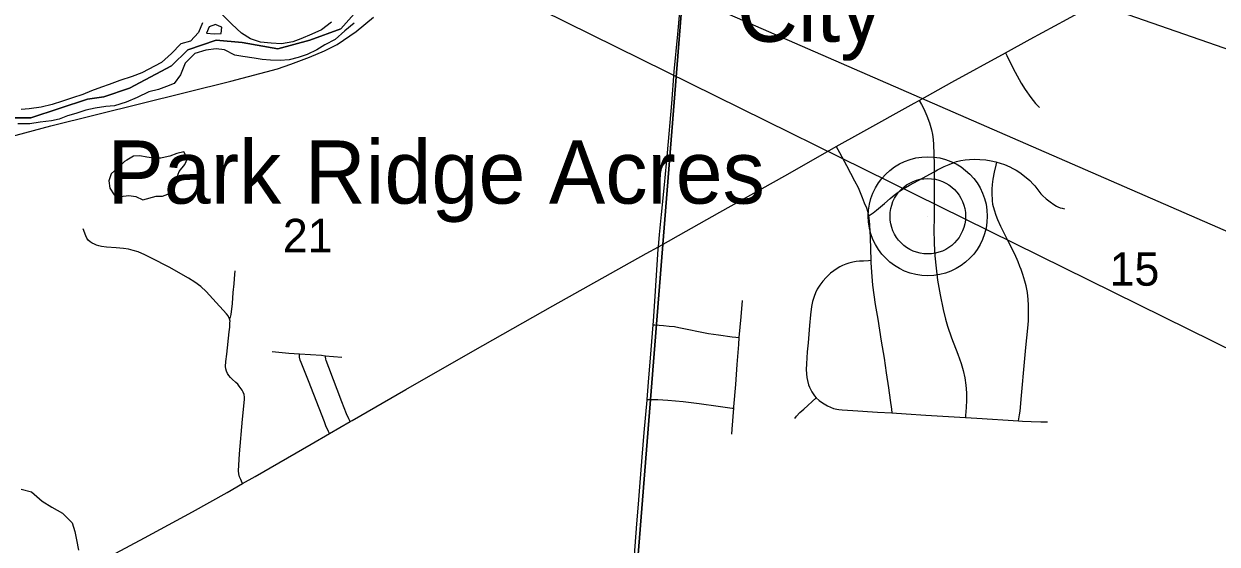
# Model space of a CAD drawing. Extents: x 0 to 34, y 0 to 22.
# Drawn here: x 5.23 to 6.722, y 16.342 to 16.993 of the extents above; entities that cross this region are included whole.
import ezdxf

# ---------------------------------------------------------------- set-up
doc = ezdxf.new("R2010")
doc.units = 0
for name, color, linetype in [('GM_X_City_Street', 7, 'Continuous'), ('GM_X_County_Road', 7, 'Continuous'), ('GM_X_Major_River', 7, 'Continuous'), ('GM_X_Minor_Lake', 7, 'Continuous'), ('GM_X_Minor_River', 7, 'Continuous'), ('GM_X_Rail_Line', 7, 'Continuous'), ('GM_X_Section', 7, 'Continuous'), ('GM_X_Section_Text', 7, 'Continuous'), ('GM_X_Township_Road', 7, 'Continuous'), ('GM_X_Unincorporated', 7, 'Continuous'), ('GM_X_Unincorporated_Location', 7, 'Continuous'), ('GM_X_Unincorporated_Text', 7, 'Continuous'), ('SH_Text', 7, 'Continuous')]:
    doc.layers.add(name, color=color, linetype=linetype)

msp = doc.modelspace()

# ---------------------------------------------------------------- linework, layer by layer
at = {"layer": 'GM_X_City_Street'}
for points in [[(5.2096, 16.875), (5.2389, 16.875), (5.3099, 16.8982), (5.33, 16.9013), (5.3624, 16.9121), (5.4149, 16.9399), (5.435, 16.9599), (5.4705, 16.9723), (5.5029, 16.9692), (5.5477, 16.9615), (5.5878, 16.9723), (5.6264, 16.9862), (5.6496, 17.0125)], [(5.6496, 17.0125), (5.6264, 16.9862), (5.5878, 16.9723), (5.5477, 16.9615), (5.5029, 16.9692), (5.4705, 16.9723), (5.435, 16.9599), (5.4149, 16.9399), (5.3624, 16.9121), (5.33, 16.9013), (5.3099, 16.8982), (5.2389, 16.875), (5.2096, 16.875)]]:
    msp.add_lwpolyline(points, dxfattribs=at)
at = {"layer": 'GM_X_County_Road'}
msp.add_line((5.6122, 16.4802), (5.6381, 16.4951), dxfattribs=at)
for points in [[(6.4571, 16.9565), (6.4879, 16.9734), (6.5342, 16.9986), (6.5737, 17.0201), (6.6055, 17.0372), (6.6328, 17.052), (6.6632, 17.0678), (6.6772, 17.0746), (6.6971, 17.0834), (6.7202, 17.0927), (6.761, 17.1079), (6.7691, 17.1109)], [(6.3494, 16.8969), (6.3901, 16.9197), (6.4571, 16.9565)], [(6.2456, 16.839), (6.2762, 16.8562), (6.3431, 16.8933), (6.3494, 16.8969)], [(6.0234, 16.7138), (6.0486, 16.7279), (6.0999, 16.7571), (6.1813, 16.8026), (6.2347, 16.8329), (6.2456, 16.839)], [(5.6381, 16.4951), (5.6404, 16.4964), (5.7077, 16.5353), (5.7912, 16.5832), (5.8914, 16.6397), (6.0079, 16.7052), (6.0234, 16.7138)], [(5.5036, 16.4175), (5.5193, 16.4265), (5.5892, 16.4669), (5.6122, 16.4802)], [(5.2978, 16.3047), (5.3453, 16.3303), (5.3808, 16.3494), (5.4408, 16.3822), (5.4842, 16.4065), (5.5036, 16.4175)]]:
    msp.add_lwpolyline(points, dxfattribs=at)
at = {"layer": 'GM_X_Major_River'}
for points in [[(5.6146, 16.9945), (5.6023, 16.9849), (5.59, 16.9798), (5.5765, 16.974), (5.5666, 16.9701), (5.5524, 16.9677), (5.5395, 16.9684), (5.5259, 16.9698), (5.5134, 16.9739), (5.5021, 16.981), (5.4901, 16.992), (5.4781, 17.0041)], [(5.4534, 16.9939), (5.4485, 16.9818), (5.4384, 16.971), (5.4265, 16.9674), (5.4149, 16.9555), (5.4021, 16.9444), (5.3778, 16.9312), (5.3655, 16.9266), (5.3502, 16.9216), (5.3368, 16.9165), (5.3272, 16.9133), (5.3149, 16.9087), (5.3038, 16.9043), (5.2911, 16.9), (5.2785, 16.8958), (5.2655, 16.8915), (5.2517, 16.8884), (5.2368, 16.8864), (5.2269, 16.8855)], [(5.6431, 16.9935), (5.6315, 16.9839), (5.6195, 16.9731), (5.6064, 16.9662), (5.5964, 16.9599), (5.5841, 16.9541), (5.573, 16.9505), (5.5619, 16.9474), (5.5504, 16.9469), (5.5383, 16.9471), (5.528, 16.9481), (5.5182, 16.9498), (5.5038, 16.9517), (5.4939, 16.9534), (5.4808, 16.9602), (5.4705, 16.9615), (5.4575, 16.9595), (5.4441, 16.9553), (5.4317, 16.9434), (5.4261, 16.929), (5.4182, 16.9178), (5.4086, 16.9142), (5.3983, 16.9106), (5.3864, 16.9075), (5.3718, 16.9006), (5.358, 16.8944), (5.3434, 16.8902), (5.3327, 16.8892), (5.3194, 16.8869), (5.3075, 16.8845), (5.2953, 16.8806), (5.2849, 16.8774), (5.2742, 16.8734), (5.2646, 16.8713), (5.2505, 16.8697)], [(5.4745, 16.9898), (5.4697, 16.9917), (5.4617, 16.9887), (5.4586, 16.9808)], [(5.4586, 16.9808), (5.4681, 16.9799), (5.4768, 16.9806), (5.4777, 16.9885), (5.4745, 16.9898)], [(5.2505, 16.8697), (5.2376, 16.8677), (5.2227, 16.8673)]]:
    msp.add_lwpolyline(points, dxfattribs=at)
at = {"layer": 'GM_X_Minor_Lake'}
for points in [[(5.4102, 16.7796), (5.4128, 16.7805), (5.4179, 16.7891), (5.4206, 16.7978), (5.4245, 16.8077), (5.4315, 16.8167), (5.4346, 16.8243), (5.4302, 16.8323), (5.4214, 16.8305), (5.4126, 16.8272), (5.4069, 16.8257), (5.4012, 16.8246), (5.3932, 16.8244), (5.3841, 16.8256), (5.375, 16.8276), (5.3674, 16.8269), (5.359, 16.8221)], [(5.359, 16.8221), (5.356, 16.8202), (5.3479, 16.8127), (5.3394, 16.8049), (5.3363, 16.7962), (5.3377, 16.787), (5.3429, 16.7786), (5.3512, 16.7766), (5.3615, 16.778), (5.3702, 16.7768), (5.3789, 16.7725), (5.3957, 16.7769), (5.4033, 16.7772), (5.4102, 16.7796)]]:
    msp.add_lwpolyline(points, dxfattribs=at)
at = {"layer": 'GM_X_Minor_River'}
msp.add_lwpolyline([(5.2267, 16.4106), (5.2399, 16.407), (5.2531, 16.3954), (5.2652, 16.3881), (5.2784, 16.3803), (5.2904, 16.3684), (5.294, 16.3574), (5.2958, 16.3471), (5.2987, 16.3342)], dxfattribs=at)
at = {"layer": 'GM_X_Rail_Line'}
msp.add_lwpolyline([(5.166, 16.8388), (5.2638, 16.8648), (5.4891, 16.921), (5.5473, 16.9364), (5.564, 16.942), (5.5874, 16.9507), (5.6058, 16.9589), (5.622, 16.9669), (5.6455, 16.9832), (5.6671, 17.001)], dxfattribs=at)
at = {"layer": 'GM_X_Section'}
for points in [[(5.0487, 17.3219), (6.0711, 17.2462), (5.9902, 16.2292), (4.9634, 16.3122)], [(6.0711, 17.2462), (7.0855, 17.1656), (6.992, 16.1486), (5.9902, 16.2292)]]:
    msp.add_lwpolyline(points, close=True, dxfattribs=at)
at = {"layer": 'GM_X_Township_Road'}
msp.add_line((5.607, 16.5774), (5.6275, 16.5756), dxfattribs=at)
for points in [[(6.0234, 16.7138), (6.0248, 16.7292), (6.0271, 16.7539), (6.0308, 16.791), (6.0348, 16.8312), (6.0401, 16.8931), (6.0432, 16.933), (6.0478, 16.9797), (6.0502, 17.0076)], [(6.4571, 16.9565), (6.4589, 16.9529), (6.4639, 16.9427), (6.4694, 16.9323), (6.4769, 16.9185), (6.4818, 16.9106), (6.489, 16.9004), (6.4948, 16.8931), (6.4996, 16.8879)], [(6.3494, 16.8969), (6.3521, 16.8916), (6.3549, 16.8861), (6.3587, 16.8776), (6.362, 16.8689), (6.3647, 16.8601), (6.366, 16.8541), (6.3668, 16.848), (6.3672, 16.8418), (6.3678, 16.817), (6.368, 16.8075)], [(6.2456, 16.839), (6.2495, 16.8318), (6.2583, 16.8153), (6.2686, 16.7961), (6.2728, 16.7878), (6.2756, 16.7817), (6.2782, 16.7754), (6.2807, 16.7688), (6.2833, 16.7623), (6.2846, 16.7582), (6.2856, 16.754), (6.2859, 16.7523)], [(6.368, 16.8075), (6.3722, 16.8099), (6.3805, 16.8141), (6.3866, 16.8168), (6.3918, 16.8189), (6.396, 16.8203), (6.4015, 16.8216), (6.4068, 16.8223), (6.4122, 16.8227), (6.4178, 16.8231), (6.4249, 16.823), (6.4327, 16.8225), (6.4392, 16.8213), (6.445, 16.8201), (6.4464, 16.8197)], [(6.4732, 16.4959), (6.4737, 16.4984), (6.4747, 16.5034), (6.4754, 16.5081), (6.4771, 16.5275), (6.481, 16.5695), (6.4827, 16.5876), (6.484, 16.5998), (6.4852, 16.6119), (6.4857, 16.6211), (6.4859, 16.6308), (6.4857, 16.6407), (6.4853, 16.6479), (6.4845, 16.6566), (6.4829, 16.6647), (6.4812, 16.6708), (6.479, 16.6789), (6.4767, 16.6854), (6.4752, 16.6892), (6.473, 16.695), (6.4687, 16.7045), (6.4604, 16.7206), (6.4513, 16.739), (6.4475, 16.7474), (6.4453, 16.7527), (6.4432, 16.7593), (6.4415, 16.7664), (6.4408, 16.7717), (6.4404, 16.7809), (6.4406, 16.7857), (6.4409, 16.7915), (6.4418, 16.7984), (6.4434, 16.8071), (6.4455, 16.8156), (6.4464, 16.8197)], [(6.4464, 16.8197), (6.4506, 16.8185), (6.4561, 16.8168), (6.4627, 16.8139), (6.4665, 16.8118), (6.4706, 16.8094), (6.475, 16.8065), (6.4828, 16.8004), (6.4876, 16.7965), (6.4919, 16.7922), (6.4939, 16.7899), (6.4976, 16.7849), (6.5014, 16.7801), (6.5036, 16.7779), (6.5081, 16.7737), (6.5128, 16.7698), (6.5175, 16.7664), (6.5208, 16.7643), (6.5227, 16.7635), (6.5254, 16.7625), (6.5279, 16.7618), (6.5307, 16.7611)], [(6.2859, 16.7523), (6.2879, 16.7536), (6.2918, 16.7561), (6.2961, 16.7594), (6.2986, 16.7616), (6.3009, 16.7635), (6.3058, 16.7679), (6.3129, 16.774), (6.3179, 16.7781), (6.3229, 16.7819), (6.3292, 16.7861), (6.337, 16.7906), (6.3533, 16.7994), (6.368, 16.8075)], [(6.368, 16.8075), (6.3678, 16.7488), (6.3677, 16.7363), (6.368, 16.7177), (6.3688, 16.7022), (6.3704, 16.6871), (6.3723, 16.6719), (6.3754, 16.6536), (6.3791, 16.6353), (6.382, 16.6233), (6.3846, 16.6143), (6.3896, 16.5996), (6.3975, 16.5794), (6.4017, 16.5677), (6.4044, 16.5588), (6.4063, 16.5497), (6.4076, 16.5404), (6.4083, 16.5311), (6.4084, 16.5218), (6.4079, 16.5126), (6.4073, 16.5027), (6.4072, 16.5)], [(6.2859, 16.7523), (6.2864, 16.7496), (6.2868, 16.746), (6.2873, 16.7407), (6.2882, 16.7252), (6.2887, 16.6965)], [(5.4869, 16.6242), (5.4861, 16.6262), (5.4854, 16.6273), (5.4834, 16.6297), (5.4665, 16.6486), (5.458, 16.6576), (5.4512, 16.6639), (5.4439, 16.6696), (5.4361, 16.6746), (5.4117, 16.6881), (5.3898, 16.6996), (5.3814, 16.7037), (5.3729, 16.7073), (5.367, 16.7092), (5.361, 16.7107), (5.3549, 16.7117), (5.3456, 16.7125), (5.3333, 16.7133), (5.3271, 16.7141), (5.3241, 16.7148), (5.3212, 16.7157), (5.3183, 16.7168), (5.3155, 16.7181), (5.3129, 16.7199), (5.3107, 16.722), (5.3089, 16.7245), (5.3075, 16.7273), (5.3043, 16.736)], [(6.0167, 16.6161), (6.017, 16.6208), (6.0194, 16.6518), (6.0231, 16.7107), (6.0234, 16.7138)], [(6.2887, 16.6965), (6.2859, 16.6963), (6.2796, 16.6959), (6.2746, 16.6956), (6.2704, 16.6952), (6.2665, 16.6946), (6.2612, 16.6933), (6.2577, 16.6921), (6.2534, 16.6903), (6.25, 16.6885), (6.2469, 16.6866), (6.2427, 16.6838), (6.2385, 16.6805), (6.2353, 16.6776), (6.233, 16.6754), (6.2289, 16.6708), (6.2251, 16.6658), (6.2234, 16.6633), (6.2219, 16.6606), (6.2196, 16.656), (6.2178, 16.6515), (6.216, 16.6453), (6.2147, 16.6389), (6.2134, 16.6286), (6.2123, 16.6153), (6.2103, 16.5936), (6.2093, 16.5824), (6.2083, 16.5673), (6.2081, 16.5602), (6.2083, 16.5546), (6.2088, 16.5502), (6.2095, 16.5465), (6.2111, 16.5409), (6.2123, 16.538), (6.2151, 16.5324), (6.2167, 16.5297), (6.2186, 16.5272), (6.2203, 16.5249)], [(6.2887, 16.6965), (6.2888, 16.6942), (6.2895, 16.6818), (6.2911, 16.6658), (6.2944, 16.6413), (6.2975, 16.6233), (6.3019, 16.5957), (6.3055, 16.5743), (6.3082, 16.5559), (6.311, 16.5374), (6.313, 16.522), (6.3145, 16.5106), (6.3151, 16.5058)], [(5.4869, 16.6242), (5.4875, 16.6246), (5.4883, 16.6256), (5.4888, 16.6272), (5.4892, 16.629), (5.4909, 16.6427), (5.492, 16.6566), (5.493, 16.6673), (5.4935, 16.6735), (5.494, 16.6792), (5.4945, 16.6836)], [(6.1244, 16.6001), (6.1267, 16.626), (6.1283, 16.6467)], [(5.5036, 16.4175), (5.5032, 16.4182), (5.5013, 16.4224), (5.4997, 16.426), (5.4987, 16.4297), (5.4983, 16.4336), (5.4998, 16.4548), (5.5033, 16.498), (5.5059, 16.5226), (5.506, 16.5257), (5.5056, 16.5288), (5.5045, 16.5317), (5.503, 16.5344), (5.4995, 16.5395), (5.4975, 16.5419), (5.4952, 16.544), (5.4905, 16.5479), (5.4883, 16.5501), (5.4864, 16.5525), (5.4847, 16.5551), (5.4834, 16.558), (5.4826, 16.5609), (5.4823, 16.564), (5.4828, 16.5702), (5.484, 16.5794), (5.4868, 16.6071), (5.4875, 16.6133), (5.4878, 16.6184), (5.4879, 16.6205), (5.4878, 16.6218), (5.4875, 16.623), (5.4869, 16.6242)], [(6.0092, 16.5228), (6.0114, 16.5496), (6.0135, 16.5744), (6.0167, 16.6161)], [(6.0167, 16.6161), (6.019, 16.6159), (6.0296, 16.6152), (6.0367, 16.6145), (6.0435, 16.6138), (6.0489, 16.6129), (6.0859, 16.6052), (6.0983, 16.6034), (6.1157, 16.6012), (6.1202, 16.6006), (6.1244, 16.6001)], [(6.1175, 16.5116), (6.1177, 16.5135), (6.1201, 16.5416), (6.1218, 16.5666), (6.1237, 16.5916), (6.1244, 16.6001)], [(5.5404, 16.5826), (5.5616, 16.5808), (5.5747, 16.5798)], [(5.6122, 16.4802), (5.6111, 16.4825), (5.6076, 16.4896), (5.6058, 16.4948), (5.5858, 16.5458), (5.5767, 16.5688), (5.5757, 16.5718), (5.5749, 16.5755), (5.5748, 16.5788), (5.5747, 16.5798)], [(5.5747, 16.5798), (5.6024, 16.5779), (5.607, 16.5774)], [(5.6381, 16.4951), (5.6365, 16.4985), (5.6335, 16.5048), (5.6277, 16.5197), (5.6114, 16.5627), (5.6081, 16.5713), (5.6077, 16.5733), (5.6072, 16.5761), (5.607, 16.5774)], [(5.9923, 16.3112), (5.9963, 16.367), (5.9983, 16.3917), (6.0001, 16.4134), (6.0031, 16.4506), (6.0056, 16.4815), (6.0091, 16.5218), (6.0092, 16.5228)], [(6.0092, 16.5228), (6.012, 16.5227), (6.0226, 16.5225), (6.035, 16.5219), (6.0542, 16.5203), (6.0741, 16.5177), (6.098, 16.5141), (6.1154, 16.5119), (6.1175, 16.5116)], [(6.1153, 16.4791), (6.1156, 16.4854), (6.1175, 16.5116)], [(6.1937, 16.4989), (6.1961, 16.5018), (6.2003, 16.5062), (6.205, 16.5107), (6.2203, 16.5249)], [(6.2203, 16.5249), (6.2241, 16.5216), (6.2272, 16.5192), (6.2304, 16.5172), (6.2348, 16.5146), (6.2383, 16.513), (6.2423, 16.5114), (6.2463, 16.5104), (6.249, 16.51), (6.253, 16.5097), (6.2662, 16.5088), (6.2973, 16.507), (6.3151, 16.5058)], [(6.3151, 16.5058), (6.3328, 16.5047), (6.3576, 16.5031), (6.4072, 16.5)], [(6.4072, 16.5), (6.4212, 16.4991), (6.4732, 16.4959)], [(6.4732, 16.4959), (6.4782, 16.4956), (6.4892, 16.4952), (6.5014, 16.4948), (6.5097, 16.4948)]]:
    msp.add_lwpolyline(points, dxfattribs=at)
at = {"layer": 'GM_X_Unincorporated'}
for radius in [0.0744, 0.0472]:
    msp.add_circle((6.36, 16.7519), radius, dxfattribs=at)
at = {"layer": 'GM_X_Unincorporated_Location'}
msp.add_line((6.36, 16.7519), (6.36, 16.7519), dxfattribs=at)
at = {"layer": 'SH_Text'}
for points in [[(9.3277, 15.6016), (4.1983, 17.8389), (9.3277, 15.3062)], [(9.3042, 16.3207), (4.2062, 17.84), (9.3042, 16.0683)]]:
    msp.add_lwpolyline(points, close=True, dxfattribs=at)

# ---------------------------------------------------------------- texts
at = {"layer": 'GM_X_Section_Text'}
for s, p in [('21', (5.5539, 16.7068)), ('15', (6.5872, 16.665))]:
    msp.add_text(s, height=0.04186, rotation=0, dxfattribs=at).set_placement(p)
at = {"layer": 'GM_X_Unincorporated_Text'}
for s, height, p in [('City', 0.07898, (6.1214, 16.9702)), ('Park Ridge Acres', 0.078977, (5.3347, 16.7677))]:
    msp.add_text(s, height=height, rotation=0, dxfattribs=at).set_placement(p)

doc.saveas('drawing.dxf')
